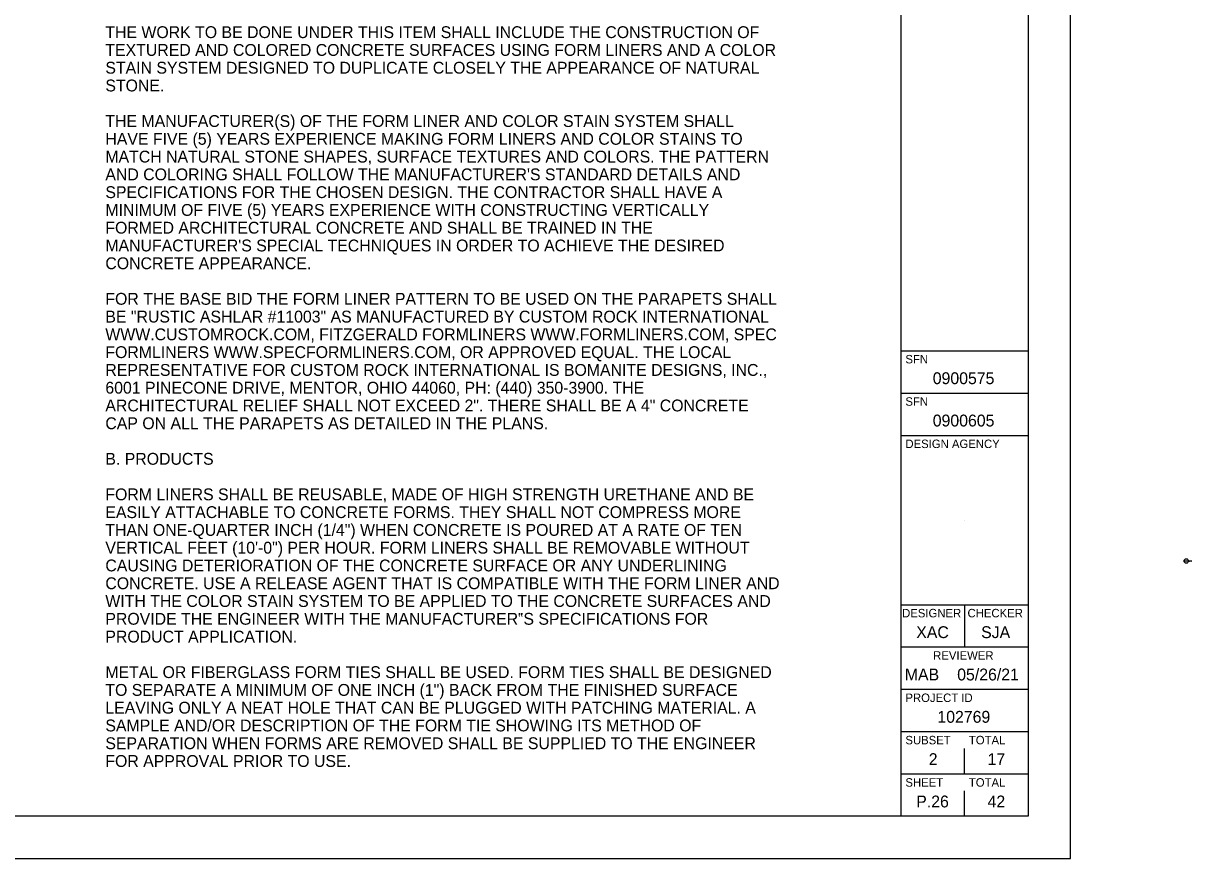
# Model space of a CAD drawing. Extents: x -17.8 to 35.4, y -13.8 to 33.2.
# Drawn here: x 21.63 to 35.43, y 0 to 9.87 of the extents above; entities that cross this region are included whole.
import ezdxf

# ---------------------------------------------------------------- set-up
doc = ezdxf.new("R2010")
doc.units = 0
for name, color, linetype in [('Default', 7, 'Continuous'), ('SH_Border', 7, 'Continuous'), ('SH_Cut_Line', 7, 'Continuous'), ('SH_Data', 7, 'Continuous')]:
    doc.layers.add(name, color=color, linetype=linetype)

msp = doc.modelspace()

# ---------------------------------------------------------------- linework, layer by layer
at = {"layer": 'Default'}
for p, q in [((35.343, 3.516), (35.395, 3.516)), ((35.369, 3.516), (35.433, 3.516))]:
    msp.add_line(p, q, dxfattribs=at)
msp.add_circle((35.369, 3.516), 0.026, dxfattribs=at)
at = {"layer": 'SH_Border'}
for p, q in [((32, 0.5), (32, 21.5)), ((32, 6), (33.5, 6)), ((32, 5.5), (33.5, 5.5)), ((32, 5), (33.5, 5)), ((32, 3), (33.5, 3)), ((32.75, 3), (32.75, 2.5)), ((32, 2.5), (33.5, 2.5)), ((32, 2), (33.5, 2)), ((32, 1.5), (33.5, 1.5)), ((32, 1), (33.5, 1))]:
    msp.add_line(p, q, dxfattribs=at)
msp.add_lwpolyline([(1.5, 21.5), (33.5, 21.5), (33.5, 0.5), (1.5, 0.5)], close=True, dxfattribs=at)
at = {"layer": 'SH_Cut_Line'}
msp.add_lwpolyline([(0, 0), (34, 0), (34, 22), (0, 22)], close=True, dxfattribs=at)
at = {"layer": 'SH_Data'}
for p, q in [((32.75, 5.675), (32.75, 5.675)), ((32.75, 5.175), (32.75, 5.175)), ((32.75, 4), (32.75, 4)), ((32.75, 1), (32.75, 1.3)), ((32.75, 0.5), (32.75, 0.8)), ((32.375, 0.675), (32.375, 0.675))]:
    msp.add_line(p, q, dxfattribs=at)

# ---------------------------------------------------------------- texts
at = {"layer": 'Default'}
for s, height, p in [('THE WORK TO BE DONE UNDER THIS ITEM SHALL INCLUDE THE CONSTRUCTION OF ', 0.14, (22.595, 9.693)), ('TEXTURED AND COLORED CONCRETE SURFACES USING FORM LINERS AND A COLOR ', 0.14, (22.595, 9.483)), ('STAIN SYSTEM DESIGNED TO DUPLICATE CLOSELY THE APPEARANCE OF NATURAL ', 0.14, (22.595, 9.273)), ('STONE.  ', 0.14, (22.595, 9.063)), ('THE MANUFACTURER(S) OF THE FORM LINER AND COLOR STAIN SYSTEM SHALL ', 0.14, (22.595, 8.643)), ('HAVE FIVE (5) YEARS EXPERIENCE MAKING FORM LINERS AND COLOR STAINS TO ', 0.14, (22.595, 8.433)), ('MATCH NATURAL STONE SHAPES, SURFACE TEXTURES AND COLORS. THE PATTERN ', 0.14, (22.595, 8.223)), ("AND COLORING SHALL FOLLOW THE MANUFACTURER'S STANDARD DETAILS AND ", 0.14, (22.595, 8.013)), ('SPECIFICATIONS FOR THE CHOSEN DESIGN. THE CONTRACTOR SHALL HAVE A ', 0.14, (22.595, 7.803)), ('MINIMUM OF FIVE (5) YEARS EXPERIENCE WITH CONSTRUCTING VERTICALLY ', 0.14, (22.595, 7.593)), ('FORMED ARCHITECTURAL CONCRETE AND SHALL BE TRAINED IN THE ', 0.14, (22.595, 7.383)), ("MANUFACTURER'S SPECIAL TECHNIQUES IN ORDER TO ACHIEVE THE DESIRED ", 0.14, (22.595, 7.173)), ('CONCRETE APPEARANCE.  ', 0.14, (22.595, 6.963)), ('FOR THE BASE BID THE FORM LINER PATTERN TO BE USED ON THE PARAPETS SHALL ', 0.14, (22.595, 6.543)), ('BE "RUSTIC ASHLAR #11003" AS MANUFACTURED BY CUSTOM ROCK INTERNATIONAL ', 0.14, (22.595, 6.333)), ('WWW.CUSTOMROCK.COM, FITZGERALD FORMLINERS WWW.FORMLINERS.COM, SPEC ', 0.14, (22.595, 6.123)), ('FORMLINERS WWW.SPECFORMLINERS.COM, OR APPROVED EQUAL. THE LOCAL ', 0.14, (22.595, 5.913)), ('REPRESENTATIVE FOR CUSTOM ROCK INTERNATIONAL IS BOMANITE DESIGNS, INC., ', 0.14, (22.595, 5.703)), ('6001 PINECONE DRIVE, MENTOR, OHIO 44060, PH: (440) 350-3900. THE ', 0.14, (22.595, 5.493)), ('ARCHITECTURAL RELIEF SHALL NOT EXCEED 2". THERE SHALL BE A 4" CONCRETE ', 0.14, (22.595, 5.283)), ('CAP ON ALL THE PARAPETS AS DETAILED IN THE PLANS.', 0.14, (22.595, 5.073)), ('B. PRODUCTS', 0.14, (22.595, 4.653)), ('FORM LINERS SHALL BE REUSABLE, MADE OF HIGH STRENGTH URETHANE AND BE', 0.14, (22.595, 4.233)), ('EASILY ATTACHABLE TO CONCRETE FORMS. THEY SHALL NOT COMPRESS MORE ', 0.14, (22.595, 4.023)), ('THAN ONE-QUARTER INCH (1/4") WHEN CONCRETE IS POURED AT A RATE OF TEN ', 0.14, (22.595, 3.813)), ('VERTICAL FEET (10\'-0") PER HOUR. FORM LINERS SHALL BE REMOVABLE WITHOUT ', 0.14, (22.595, 3.603)), ('CAUSING DETERIORATION OF THE CONCRETE SURFACE OR ANY UNDERLINING ', 0.14, (22.595, 3.393)), ('P.26', 0.00328, (35.365, 3.506)), ('1', 0.00328, (35.368, 3.523)), ('Drawing', 0.00328, (35.402, 3.523)), ('CUSTOM 4.5:1', 0.00328, (35.402, 3.506)), ('CONCRETE. USE A RELEASE AGENT THAT IS COMPATIBLE WITH THE FORM LINER AND ', 0.14, (22.595, 3.183)), ('WITH THE COLOR STAIN SYSTEM TO BE APPLIED TO THE CONCRETE SURFACES AND ', 0.14, (22.595, 2.973)), ('PROVIDE THE ENGINEER WITH THE MANUFACTURER‟S SPECIFICATIONS FOR ', 0.14, (22.595, 2.763)), ('PRODUCT APPLICATION.', 0.14, (22.595, 2.553)), ('METAL OR FIBERGLASS FORM TIES SHALL BE USED. FORM TIES SHALL BE DESIGNED ', 0.14, (22.595, 2.133)), ('TO SEPARATE A MINIMUM OF ONE INCH (1") BACK FROM THE FINISHED SURFACE', 0.14, (22.595, 1.923)), ('LEAVING ONLY A NEAT HOLE THAT CAN BE PLUGGED WITH PATCHING MATERIAL. A', 0.14, (22.595, 1.713)), ('SAMPLE AND/OR DESCRIPTION OF THE FORM TIE SHOWING ITS METHOD OF ', 0.14, (22.595, 1.503)), ('SEPARATION WHEN FORMS ARE REMOVED SHALL BE SUPPLIED TO THE ENGINEER ', 0.14, (22.595, 1.293)), ('FOR APPROVAL PRIOR TO USE.', 0.14, (22.595, 1.083))]:
    msp.add_text(s, height=height, dxfattribs=at).set_placement(p)
at = {"layer": 'SH_Data'}
for s, height, p in [('SFN', 0.1, (32.05, 5.85)), ('0900575', 0.14, (32.373, 5.605)), ('SFN', 0.1, (32.05, 5.35)), ('0900605', 0.14, (32.373, 5.105)), ('DESIGN AGENCY', 0.1, (32.05, 4.85)), ('DESIGNER', 0.1, (32.011, 2.85)), ('CHECKER', 0.1, (32.784, 2.85)), ('XAC', 0.14, (32.178, 2.605)), ('SJA', 0.14, (32.945, 2.605)), ('REVIEWER', 0.1, (32.378, 2.35)), ('MAB', 0.14, (32.043, 2.105)), ('05/26/21', 0.14, (32.662, 2.105)), ('PROJECT ID', 0.1, (32.05, 1.85)), ('102769', 0.14, (32.428, 1.605)), ('SUBSET', 0.1, (32.05, 1.35)), ('TOTAL', 0.1, (32.8, 1.35)), ('2', 0.14, (32.326, 1.105)), ('17', 0.14, (33.021, 1.105)), ('SHEET', 0.1, (32.05, 0.85)), ('TOTAL', 0.1, (32.8, 0.85)), ('P.26', 0.14, (32.178, 0.605)), ('42', 0.14, (33.021, 0.605))]:
    msp.add_text(s, height=height, dxfattribs=at).set_placement(p)

doc.saveas('drawing.dxf')
